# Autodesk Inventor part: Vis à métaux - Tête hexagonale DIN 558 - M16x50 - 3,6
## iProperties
Created: 2002-04
Part Number: Vis à métaux - Tête hexagonale DIN 558 - M16x50 - 3,6
Material: Par défaut
Catalog Web Link: www.traceparts.com
Description: Vis à métaux - Tête hexagonale DIN 558 - M16x50 - 3,6
Document SubType Name: Modélisation
Designer: Maison
Control State: 0
Master: False
Checked Out: False
Shininess: 20.0
Length Units: 11269
Angle Units: 11279
Time Units: 11290
Mass Units: 11283
Length Display Precision: 3
Angle Display Precision: 2
Density: 0.0
Volumn: 0.0
Area: 0.0
PropertySet Name: Model Information
Author: Maison
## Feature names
1. Base1
